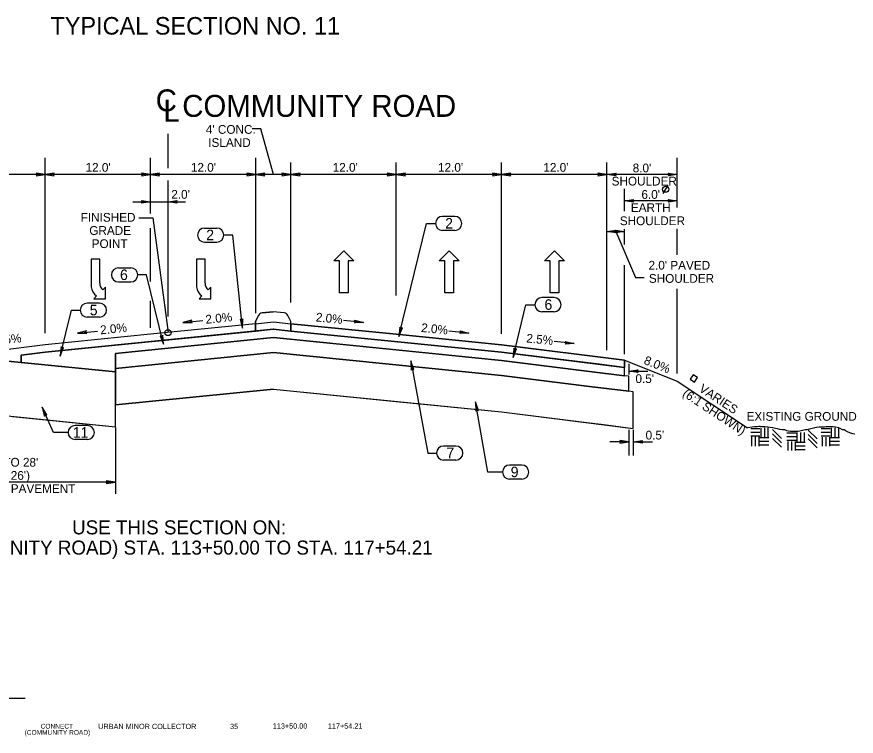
# Model space of a CAD drawing. Extents: x 2003207 to 2014043, y 843846 to 860154.
# Drawn here: x 2013867.8 to 2013963.4, y 844813 to 844894.9 of the extents above; entities that cross this region are included whole.
import ezdxf

# ---------------------------------------------------------------- set-up
doc = ezdxf.new("R2010")
doc.units = 0
for name, color, linetype in [('RD_EX_Road', 7, 'Continuous'), ('RD_EX_Road_txCode', 7, 'Continuous'), ('RD_PD_ConcMed', 7, 'Continuous'), ('RD_QTY_Base_Course', 7, 'Continuous'), ('RD_QTY_ConcPave', 7, 'Continuous'), ('RD_QTY_Intermediate', 7, 'Continuous'), ('RD_QTY_PermVeg', 7, 'Continuous'), ('RD_QTY_Surf_Course', 7, 'Continuous'), ('RD_SHT_Bndy', 7, 'Continuous'), ('RD_SHT_TX', 7, 'Continuous'), ('RD_TX_Misc1', 7, 'Continuous'), ('RD_TX_Misc2', 7, 'Continuous'), ('RD_TX_TypSect', 7, 'Continuous'), ('RD_XS_ExGround', 7, 'Continuous')]:
    doc.layers.add(name, color=color, linetype=linetype)

msp = doc.modelspace()

# ---------------------------------------------------------------- linework, layer by layer
at = {"layer": 'RD_EX_Road'}
for p, q in [((2013879.048, 844854.476), (2013866.048, 844855.776)), ((2013879.048, 844848.226), (2013879.048, 844854.476)), ((2013866.048, 844849.526), (2013879.048, 844848.226)), ((2013867.324, 844849.398), (2013879.048, 844848.226))]:
    msp.add_line(p, q, dxfattribs=at)
at = {"layer": 'RD_EX_Road_txCode'}
msp.add_lwpolyline([(2013944.528, 844853.649), (2013945.028, 844853.318), (2013945.36, 844853.818), (2013944.86, 844854.15)], close=True, dxfattribs=at)
msp.add_circle((2013885.049, 844858.959), 0.35, dxfattribs=at)
at = {"layer": 'RD_PD_ConcMed'}
for p, q in [((2013895.024, 844860.207), (2013895.357, 844860.913)), ((2013895.357, 844860.913), (2013895.024, 844860.207)), ((2013895.76, 844861.197), (2013897.024, 844861.324)), ((2013897.024, 844861.324), (2013895.76, 844861.197)), ((2013898.289, 844861.197), (2013897.024, 844861.324)), ((2013898.289, 844861.197), (2013897.024, 844861.324)), ((2013899.024, 844860.207), (2013898.691, 844860.913)), ((2013899.024, 844860.207), (2013898.691, 844860.913)), ((2013895.024, 844859.124), (2013895.024, 844860.207)), ((2013895.024, 844860.207), (2013895.024, 844859.124)), ((2013899.024, 844859.124), (2013899.024, 844860.207)), ((2013899.024, 844859.124), (2013899.024, 844860.207)), ((2013895.024, 844859.124), (2013897.024, 844859.324)), ((2013895.024, 844859.124), (2013897.024, 844859.324)), ((2013899.024, 844859.124), (2013897.024, 844859.324)), ((2013897.024, 844859.324), (2013899.024, 844859.124))]:
    msp.add_line(p, q, dxfattribs=at)
for centre, start, end in [((2013895.809, 844860.7), 95.71059, 154.75255), ((2013895.809, 844860.7), 95.71059, 154.75255), ((2013898.239, 844860.7), 25.24745, 84.28941), ((2013898.239, 844860.7), 25.24745, 84.28941)]:
    msp.add_arc(centre, 0.5, start, end, dxfattribs=at)
at = {"layer": 'RD_QTY_Base_Course'}
for p, q in [((2013937.048, 844854.029), (2013933.048, 844854.529)), ((2013937.548, 844853.967), (2013937.048, 844854.029)), ((2013937.548, 844852.262), (2013937.548, 844853.967)), ((2013897.048, 844852.507), (2013879.048, 844850.707)), ((2013897.048, 844852.507), (2013911.048, 844851.107)), ((2013933.048, 844852.824), (2013937.548, 844852.262)), ((2013937.548, 844852.262), (2013933.048, 844852.824)), ((2013938.048, 844852.199), (2013937.548, 844852.262)), ((2013938.048, 844852.199), (2013937.548, 844852.262)), ((2013938.048, 844848.032), (2013938.048, 844852.199)), ((2013938.048, 844848.032), (2013938.048, 844852.199)), ((2013911.048, 844851.107), (2013923.048, 844849.907)), ((2013923.048, 844849.907), (2013938.048, 844848.032))]:
    msp.add_line(p, q, dxfattribs=at)
for points in [[(2013933.048, 844854.529), (2013923.048, 844855.779), (2013897.048, 844858.379), (2013879.048, 844856.579), (2013879.048, 844854.874), (2013897.048, 844856.674), (2013923.048, 844854.074), (2013933.048, 844852.824)], [(2013933.048, 844852.824), (2013923.048, 844854.074), (2013897.048, 844856.674), (2013879.048, 844854.874), (2013879.048, 844850.707), (2013897.048, 844852.507), (2013923.048, 844849.907), (2013933.048, 844848.657)], [(2013933.048, 844848.657), (2013934.373, 844848.525), (2013938.048, 844848.032)]]:
    msp.add_lwpolyline(points, dxfattribs=at)
at = {"layer": 'RD_QTY_ConcPave'}
for p, q in [((2013868.307, 844856.383), (2013868.307, 844855.55)), ((2013897.048, 844856.674), (2013879.048, 844854.874)), ((2013897.048, 844856.674), (2013911.048, 844855.274)), ((2013911.048, 844855.274), (2013923.048, 844854.074)), ((2013879.048, 844854.874), (2013879.048, 844850.707)), ((2013923.048, 844854.074), (2013937.548, 844852.262)), ((2013937.548, 844853.967), (2013937.048, 844854.029)), ((2013937.548, 844852.262), (2013937.548, 844853.967))]:
    msp.add_line(p, q, dxfattribs=at)
at = {"layer": 'RD_QTY_Intermediate'}
for p, q in [((2013895.024, 844859.124), (2013871.048, 844856.726)), ((2013897.024, 844859.324), (2013895.024, 844859.124)), ((2013899.024, 844859.124), (2013897.024, 844859.324)), ((2013923.048, 844856.726), (2013899.024, 844859.128)), ((2013899.024, 844859.128), (2013899.024, 844859.124)), ((2013897.048, 844858.379), (2013879.048, 844856.579)), ((2013879.048, 844856.579), (2013897.048, 844858.379)), ((2013897.048, 844858.379), (2013911.048, 844856.979)), ((2013897.048, 844858.379), (2013911.048, 844856.979)), ((2013871.048, 844856.726), (2013868.307, 844856.383)), ((2013879.048, 844856.579), (2013879.048, 844854.874)), ((2013879.048, 844854.476), (2013879.048, 844856.579)), ((2013911.048, 844856.979), (2013923.048, 844855.779)), ((2013911.048, 844856.979), (2013923.048, 844855.779)), ((2013934.145, 844855.339), (2013923.048, 844856.726)), ((2013923.048, 844855.779), (2013937.048, 844854.029)), ((2013923.048, 844855.779), (2013933.048, 844854.529)), ((2013937.048, 844854.976), (2013934.145, 844855.339)), ((2013933.048, 844854.529), (2013937.048, 844854.029)), ((2013937.048, 844854.029), (2013937.048, 844854.976)), ((2013937.048, 844854.029), (2013937.048, 844854.976))]:
    msp.add_line(p, q, dxfattribs=at)
msp.add_lwpolyline([(2013868.307, 844856.383), (2013868.307, 844855.55), (2013879.048, 844854.476)], dxfattribs=at)
msp.add_lwpolyline([(2013912.721, 844855.73), (2013912.759, 844854.681), (2013912.878, 844854.865), (2013913.054, 844854.734)], close=True, dxfattribs=at)
at = {"layer": 'RD_QTY_PermVeg'}
for p, q in [((2013937.048, 844855.809), (2013943.048, 844853.409)), ((2013943.048, 844853.409), (2013951.048, 844848.107))]:
    msp.add_line(p, q, dxfattribs=at)
at = {"layer": 'RD_QTY_Surf_Course'}
for p, q in [((2013895.024, 844859.957), (2013883.048, 844858.759)), ((2013895.024, 844859.957), (2013883.048, 844858.759)), ((2013895.024, 844859.957), (2013897.048, 844860.159)), ((2013895.024, 844859.957), (2013895.024, 844859.124)), ((2013895.024, 844859.124), (2013895.024, 844859.957)), ((2013897.048, 844860.159), (2013899.024, 844859.957)), ((2013899.024, 844859.962), (2013911.048, 844858.759)), ((2013911.048, 844858.759), (2013899.024, 844859.962)), ((2013899.024, 844859.957), (2013899.024, 844859.128)), ((2013897.048, 844859.326), (2013871.048, 844856.726)), ((2013871.048, 844856.726), (2013895.024, 844859.124)), ((2013897.048, 844859.326), (2013923.048, 844856.726)), ((2013899.024, 844859.128), (2013923.048, 844856.726)), ((2013883.048, 844858.759), (2013871.048, 844857.559)), ((2013883.048, 844858.759), (2013871.048, 844857.559)), ((2013911.048, 844858.759), (2013923.048, 844857.559)), ((2013923.048, 844857.559), (2013911.048, 844858.759)), ((2013871.048, 844857.559), (2013845.048, 844854.309)), ((2013871.048, 844857.559), (2013845.048, 844854.309)), ((2013923.048, 844857.559), (2013937.048, 844855.809)), ((2013937.048, 844855.809), (2013923.048, 844857.559)), ((2013871.048, 844856.726), (2013868.307, 844856.383)), ((2013923.048, 844856.726), (2013937.048, 844854.976)), ((2013923.048, 844856.726), (2013937.048, 844854.976)), ((2013937.048, 844855.809), (2013937.048, 844854.976)), ((2013937.048, 844854.976), (2013937.048, 844855.809))]:
    msp.add_line(p, q, dxfattribs=at)
for points in [[(2013899.024, 844859.962), (2013899.024, 844859.957), (2013899.024, 844859.128)], [(2013845.048, 844853.476), (2013853.048, 844854.476), (2013866.048, 844855.776), (2013868.307, 844855.55), (2013868.307, 844856.383), (2013871.048, 844856.726)]]:
    msp.add_lwpolyline(points, dxfattribs=at)
at = {"layer": 'RD_SHT_Bndy'}
msp.add_line((2013868.755, 844817.242), (2013845.755, 844817.242), dxfattribs=at)
at = {"layer": 'RD_TX_Misc2'}
for p, q in [((2013917.712, 844872.191), (2013916.312, 844872.191)), ((2013889.205, 844870.865), (2013890.605, 844870.865)), ((2013917.712, 844870.591), (2013916.312, 844870.591)), ((2013889.205, 844869.265), (2013890.605, 844869.265)), ((2013879.396, 844866.325), (2013880.796, 844866.325)), ((2013879.396, 844864.725), (2013880.796, 844864.725)), ((2013929.032, 844862.933), (2013927.632, 844862.933)), ((2013877.245, 844862.31), (2013875.845, 844862.31)), ((2013929.032, 844861.333), (2013927.632, 844861.333)), ((2013877.245, 844860.71), (2013875.845, 844860.71)), ((2013875.855, 844848.364), (2013874.455, 844848.364)), ((2013875.855, 844846.764), (2013874.455, 844846.764)), ((2013917.839, 844846.026), (2013916.439, 844846.026)), ((2013917.839, 844844.426), (2013916.439, 844844.426)), ((2013925.346, 844843.857), (2013923.946, 844843.857)), ((2013925.346, 844842.257), (2013923.946, 844842.257))]:
    msp.add_line(p, q, dxfattribs=at)
for centre, start, end in [((2013916.312, 844871.391), 90, 270), ((2013917.712, 844871.391), 270, 90), ((2013889.205, 844870.065), 90, 270), ((2013890.605, 844870.065), 270, 90), ((2013879.396, 844865.525), 90, 270), ((2013880.796, 844865.525), 270, 90), ((2013927.632, 844862.133), 90, 270), ((2013929.032, 844862.133), 270, 90), ((2013875.845, 844861.51), 90, 270), ((2013877.245, 844861.51), 270, 90), ((2013874.455, 844847.564), 90, 270), ((2013875.855, 844847.564), 270, 90), ((2013916.439, 844845.226), 90, 270), ((2013917.839, 844845.226), 270, 90), ((2013923.946, 844843.057), 90, 270), ((2013925.346, 844843.057), 270, 90)]:
    msp.add_arc(centre, 0.8, start, end, dxfattribs=at)
at = {"layer": 'RD_TX_TypSect'}
for p, q in [((2013885.049, 844877.676), (2013885.049, 844881.6)), ((2013871.048, 844858.876), (2013871.048, 844878.87)), ((2013883.048, 844872.523), (2013883.048, 844878.87)), ((2013895.048, 844861.182), (2013895.048, 844878.886)), ((2013899.048, 844862.366), (2013899.048, 844878.354)), ((2013911.048, 844863.165), (2013911.048, 844878.354)), ((2013923.048, 844858.816), (2013923.048, 844878.354)), ((2013935.048, 844856.964), (2013935.048, 844878.354)), ((2013943.048, 844873.213), (2013943.048, 844878.87)), ((2013871.048, 844876.963), (2013859.048, 844876.963)), ((2013883.048, 844876.963), (2013871.048, 844876.963)), ((2013895.048, 844876.963), (2013883.048, 844876.963)), ((2013885.049, 844860.768), (2013885.049, 844876.298)), ((2013899.048, 844876.963), (2013895.048, 844876.963)), ((2013911.048, 844876.963), (2013899.048, 844876.963)), ((2013923.048, 844876.963), (2013911.048, 844876.963)), ((2013935.048, 844876.963), (2013923.048, 844876.963)), ((2013943.048, 844876.963), (2013935.048, 844876.963)), ((2013937.048, 844872.778), (2013937.048, 844875.317)), ((2013941.451, 844874.819), (2013942.017, 844875.763)), ((2013881.048, 844873.853), (2013883.048, 844873.853)), ((2013883.048, 844873.853), (2013885.048, 844873.853)), ((2013885.048, 844873.853), (2013887.048, 844873.853)), ((2013943.048, 844873.963), (2013937.048, 844873.963)), ((2013883.048, 844864.767), (2013883.048, 844870.865)), ((2013935.048, 844870.463), (2013937.048, 844870.463)), ((2013937.048, 844869.005), (2013937.048, 844870.735)), ((2013943.048, 844867.806), (2013943.048, 844870.763)), ((2013876.275, 844867.326), (2013876.275, 844864.161)), ((2013877.265, 844867.326), (2013876.275, 844867.326)), ((2013877.265, 844864.581), (2013877.265, 844867.326)), ((2013888.275, 844867.326), (2013888.275, 844864.161)), ((2013889.265, 844867.326), (2013888.275, 844867.326)), ((2013889.265, 844864.581), (2013889.265, 844867.326)), ((2013937.048, 844856.507), (2013937.048, 844866.622)), ((2013877.925, 844864.146), (2013877.61, 844863.831)), ((2013877.91, 844862.796), (2013877.925, 844864.146)), ((2013889.925, 844864.146), (2013889.61, 844863.831)), ((2013889.91, 844862.796), (2013889.925, 844864.146)), ((2013943.048, 844854.274), (2013943.048, 844863.943)), ((2013876.905, 844863.126), (2013876.59, 844862.811)), ((2013876.59, 844862.811), (2013877.91, 844862.796)), ((2013888.905, 844863.126), (2013888.59, 844862.811)), ((2013888.59, 844862.811), (2013889.91, 844862.796)), ((2013883.048, 844859.477), (2013883.048, 844862.569)), ((2013886.729, 844860.096), (2013889.005, 844860.324)), ((2013907.32, 844860.096), (2013905.043, 844860.324)), ((2013874.729, 844858.896), (2013877.005, 844859.124)), ((2013919.32, 844858.896), (2013917.043, 844859.124)), ((2013931.32, 844857.696), (2013929.043, 844857.924)), ((2013937.548, 844855.403), (2013937.548, 844854.175)), ((2013937.548, 844854.544), (2013939.716, 844854.544)), ((2013879.048, 844848.146), (2013879.048, 844840.58)), ((2013937.548, 844847.875), (2013937.548, 844844.962)), ((2013938.048, 844847.875), (2013938.048, 844844.962)), ((2013937.548, 844846.503), (2013935.38, 844846.503)), ((2013938.048, 844846.503), (2013940.216, 844846.503)), ((2013879.048, 844841.898), (2013853.048, 844841.898))]:
    msp.add_line(p, q, dxfattribs=at)
for points in [[(2013897.048, 844876.963), (2013895.625, 844882.181), (2013894.637, 844882.181)], [(2013881.731, 844872.046), (2013883.301, 844872.046), (2013885.049, 844858.959)], [(2013911.352, 844858.518), (2013914.503, 844871.391), (2013915.512, 844871.391)], [(2013936.048, 844870.463), (2013938.288, 844865.217), (2013939.276, 844865.217)], [(2013893.512, 844859.471), (2013892.414, 844870.065), (2013891.405, 844870.065)], [(2013884.539, 844857.626), (2013882.605, 844865.525), (2013881.596, 844865.525)], [(2013924.351, 844856.119), (2013925.823, 844862.133), (2013926.832, 844862.133)], [(2013872.754, 844856.27), (2013874.037, 844861.51), (2013875.045, 844861.51)], [(2013912.721, 844855.73), (2013914.63, 844845.226), (2013915.639, 844845.226)], [(2013873.655, 844847.564), (2013871.989, 844847.564), (2013870.692, 844850.456)], [(2013923.146, 844843.057), (2013921.481, 844843.057), (2013920.067, 844851.055)]]:
    msp.add_lwpolyline(points, dxfattribs=at)
for points in [[(2013871.048, 844876.963), (2013870.009, 844877.113), (2013870.169, 844876.963), (2013870.009, 844876.813)], [(2013871.048, 844876.963), (2013872.087, 844876.813), (2013871.927, 844876.963), (2013872.087, 844877.113)], [(2013883.048, 844876.963), (2013882.009, 844877.113), (2013882.169, 844876.963), (2013882.009, 844876.813)], [(2013883.048, 844876.963), (2013884.087, 844876.813), (2013883.927, 844876.963), (2013884.087, 844877.113)], [(2013895.048, 844876.963), (2013894.009, 844877.113), (2013894.169, 844876.963), (2013894.009, 844876.813)], [(2013895.048, 844876.963), (2013896.087, 844876.813), (2013895.927, 844876.963), (2013896.087, 844877.113)], [(2013899.048, 844876.963), (2013898.009, 844877.113), (2013898.169, 844876.963), (2013898.009, 844876.813)], [(2013899.048, 844876.963), (2013900.087, 844876.813), (2013899.927, 844876.963), (2013900.087, 844877.113)], [(2013911.048, 844876.963), (2013910.009, 844877.113), (2013910.169, 844876.963), (2013910.009, 844876.813)], [(2013911.048, 844876.963), (2013912.087, 844876.813), (2013911.927, 844876.963), (2013912.087, 844877.113)], [(2013923.048, 844876.963), (2013922.009, 844877.113), (2013922.169, 844876.963), (2013922.009, 844876.813)], [(2013923.048, 844876.963), (2013924.087, 844876.813), (2013923.927, 844876.963), (2013924.087, 844877.113)], [(2013935.048, 844876.963), (2013934.009, 844877.113), (2013934.169, 844876.963), (2013934.009, 844876.813)], [(2013935.048, 844876.963), (2013936.087, 844877.113), (2013935.927, 844876.963), (2013936.087, 844876.813)], [(2013943.048, 844876.963), (2013942.009, 844876.813), (2013942.169, 844876.963), (2013942.009, 844877.113)], [(2013883.048, 844873.853), (2013882.009, 844873.703), (2013882.169, 844873.853), (2013882.009, 844874.003)], [(2013885.048, 844873.853), (2013886.087, 844874.003), (2013885.927, 844873.853), (2013886.087, 844873.703)], [(2013937.048, 844873.963), (2013938.087, 844874.113), (2013937.927, 844873.963), (2013938.087, 844873.813)], [(2013943.048, 844873.963), (2013942.009, 844873.813), (2013942.169, 844873.963), (2013942.009, 844874.113)], [(2013935.048, 844870.463), (2013936.087, 844870.613), (2013935.927, 844870.463), (2013936.087, 844870.313)], [(2013937.048, 844870.463), (2013936.009, 844870.313), (2013936.169, 844870.463), (2013936.009, 844870.613)], [(2013905.552, 844863.471), (2013904.592, 844863.471), (2013904.592, 844867.14), (2013903.941, 844867.14), (2013905.072, 844868.271), (2013906.204, 844867.14), (2013905.552, 844867.14)], [(2013917.552, 844863.471), (2013916.592, 844863.471), (2013916.592, 844867.14), (2013915.941, 844867.14), (2013917.072, 844868.271), (2013918.204, 844867.14), (2013917.552, 844867.14)], [(2013929.552, 844863.471), (2013928.592, 844863.471), (2013928.592, 844867.14), (2013927.941, 844867.14), (2013929.072, 844868.271), (2013930.204, 844867.14), (2013929.552, 844867.14)], [(2013886.729, 844860.096), (2013887.777, 844860.051), (2013887.603, 844860.184), (2013887.747, 844860.349)], [(2013893.512, 844859.471), (2013893.55, 844860.52), (2013893.418, 844860.345), (2013893.252, 844860.488)], [(2013907.32, 844860.096), (2013906.271, 844860.051), (2013906.446, 844860.184), (2013906.301, 844860.349)], [(2013874.729, 844858.896), (2013875.777, 844858.851), (2013875.603, 844858.984), (2013875.747, 844859.149)], [(2013911.352, 844858.518), (2013911.745, 844859.491), (2013911.561, 844859.372), (2013911.453, 844859.563)], [(2013919.32, 844858.896), (2013918.271, 844858.851), (2013918.446, 844858.984), (2013918.301, 844859.149)], [(2013884.539, 844857.626), (2013884.438, 844858.671), (2013884.33, 844858.48), (2013884.146, 844858.599)], [(2013872.754, 844856.27), (2013873.147, 844857.243), (2013872.963, 844857.124), (2013872.855, 844857.315)], [(2013924.351, 844856.119), (2013924.743, 844857.093), (2013924.56, 844856.973), (2013924.452, 844857.164)], [(2013931.32, 844857.696), (2013930.271, 844857.651), (2013930.446, 844857.784), (2013930.301, 844857.949)], [(2013937.548, 844854.544), (2013938.587, 844854.694), (2013938.427, 844854.544), (2013938.587, 844854.394)], [(2013870.692, 844850.456), (2013870.977, 844849.446), (2013871.049, 844849.653), (2013871.251, 844849.568)], [(2013920.067, 844851.055), (2013920.1, 844850.006), (2013920.22, 844850.19), (2013920.395, 844850.059)], [(2013937.548, 844846.503), (2013936.509, 844846.653), (2013936.669, 844846.503), (2013936.509, 844846.353)], [(2013938.048, 844846.503), (2013939.087, 844846.653), (2013938.927, 844846.503), (2013939.087, 844846.353)], [(2013879.048, 844841.898), (2013878.009, 844842.048), (2013878.169, 844841.898), (2013878.009, 844841.749)]]:
    msp.add_lwpolyline(points, close=True, dxfattribs=at)
msp.add_circle((2013941.734, 844875.291), 0.35, dxfattribs=at)
for centre, radius, start, end in [((2013877.828, 844864.398), 1.576, 188.67607, 233.98777), ((2013878.243, 844864.578), 0.983, 180, 229.65817), ((2013889.828, 844864.398), 1.576, 188.67607, 233.98777), ((2013890.243, 844864.578), 0.983, 180, 229.65817)]:
    msp.add_arc(centre, radius, start, end, dxfattribs=at)
at = {"layer": 'RD_XS_ExGround'}
for p, q in [((2013952.461, 844847.995), (2013951.42, 844847.995)), ((2013952.461, 844847.578), (2013951.42, 844847.578)), ((2013952.558, 844848.092), (2013952.558, 844847.05)), ((2013952.974, 844848.092), (2013952.974, 844847.05)), ((2013953.391, 844848.092), (2013953.391, 844847.05)), ((2013954.914, 844846.901), (2013953.914, 844847.901)), ((2013956.598, 844847.476), (2013955.556, 844847.476)), ((2013956.694, 844847.573), (2013956.694, 844846.532)), ((2013957.111, 844847.573), (2013957.111, 844846.532)), ((2013957.527, 844847.573), (2013957.527, 844846.532)), ((2013958.982, 844846.828), (2013957.982, 844847.828)), ((2013960.488, 844847.99), (2013959.446, 844847.99)), ((2013960.488, 844847.573), (2013959.446, 844847.573)), ((2013960.585, 844848.087), (2013960.585, 844847.045)), ((2013961.001, 844848.087), (2013961.001, 844847.045)), ((2013961.418, 844848.087), (2013961.418, 844847.045)), ((2013952.461, 844847.162), (2013951.42, 844847.162)), ((2013951.524, 844847.057), (2013951.524, 844846.016)), ((2013951.941, 844847.057), (2013951.941, 844846.016)), ((2013952.357, 844847.057), (2013952.357, 844846.016)), ((2013953.503, 844846.953), (2013952.461, 844846.953)), ((2013953.503, 844846.537), (2013952.461, 844846.537)), ((2013954.914, 844846.401), (2013953.914, 844847.401)), ((2013954.914, 844845.901), (2013953.914, 844846.901)), ((2013956.598, 844847.06), (2013955.556, 844847.06)), ((2013956.598, 844846.643), (2013955.556, 844846.643)), ((2013955.66, 844846.539), (2013955.66, 844845.497)), ((2013956.077, 844846.539), (2013956.077, 844845.497)), ((2013956.493, 844846.539), (2013956.493, 844845.497)), ((2013958.982, 844846.328), (2013957.982, 844847.328)), ((2013958.982, 844845.828), (2013957.982, 844846.828)), ((2013960.488, 844847.157), (2013959.446, 844847.157)), ((2013959.551, 844847.053), (2013959.551, 844846.011)), ((2013959.967, 844847.053), (2013959.967, 844846.011)), ((2013960.384, 844847.053), (2013960.384, 844846.011)), ((2013961.53, 844846.948), (2013960.488, 844846.948)), ((2013961.53, 844846.532), (2013960.488, 844846.532)), ((2013953.503, 844846.12), (2013952.461, 844846.12)), ((2013957.639, 844846.435), (2013956.598, 844846.435)), ((2013957.639, 844846.018), (2013956.598, 844846.018)), ((2013957.639, 844845.601), (2013956.598, 844845.601)), ((2013961.53, 844846.115), (2013960.488, 844846.115))]:
    msp.add_line(p, q, dxfattribs=at)
msp.add_lwpolyline([(2013963.274, 844847.375), (2013963.054, 844847.411), (2013962.835, 844847.485), (2013962.542, 844847.595), (2013962.285, 844847.704), (2013962.066, 844847.851), (2013961.883, 844847.888), (2013961.627, 844848.034), (2013961.407, 844848.107), (2013961.078, 844848.181), (2013960.821, 844848.217), (2013960.528, 844848.217), (2013960.199, 844848.217), (2013960.016, 844848.217), (2013959.833, 844848.181), (2013959.613, 844848.181), (2013959.394, 844848.181), (2013959.211, 844848.181), (2013958.918, 844848.144), (2013958.735, 844848.107), (2013958.405, 844848.034), (2013958.113, 844847.961), (2013957.82, 844847.888), (2013957.637, 844847.851), (2013957.307, 844847.778), (2013957.015, 844847.704), (2013956.795, 844847.668), (2013956.612, 844847.668), (2013956.392, 844847.668), (2013956.173, 844847.668), (2013955.953, 844847.668), (2013955.733, 844847.704), (2013955.55, 844847.741), (2013955.294, 844847.851), (2013955.038, 844847.888), (2013954.745, 844847.924), (2013954.489, 844847.997), (2013954.233, 844848.034), (2013953.94, 844848.107), (2013953.647, 844848.144), (2013953.354, 844848.181), (2013953.025, 844848.217), (2013952.732, 844848.217), (2013952.512, 844848.254), (2013952.329, 844848.254), (2013952.146, 844848.217), (2013951.853, 844848.217), (2013951.597, 844848.181), (2013951.341, 844848.144), (2013951.048, 844848.107)], dxfattribs=at)

# ---------------------------------------------------------------- texts
at = {"layer": 'RD_EX_Road_txCode'}
for s, p in [('USE THIS SECTION ON:', (2013874.116, 844835.955)), ('CONNECT (S-2885 COMMUNITY ROAD) STA. 113+50.00 TO STA. 117+54.21', (2013839.325, 844833.649))]:
    msp.add_text(s, height=1.6, dxfattribs=at).set_placement(p)
at = {"layer": 'RD_SHT_TX'}
for s, height, p in [('CONNECT ', 0.5415, (2013870.534, 844813.822)), ('URBAN MINOR COLLECTOR', 0.6, (2013877.091, 844813.768)), ('35', 0.6, (2013892.109, 844813.768)), ('113+50.00', 0.6, (2013896.976, 844813.817)), ('117+54.21', 0.6, (2013903.254, 844813.817)), ('(COMMUNITY ROAD)', 0.5415, (2013868.706, 844813.117))]:
    msp.add_text(s, height=height, dxfattribs=at).set_placement(p)
at = {"layer": 'RD_TX_Misc1'}
for s, p in [('C', (2013883.64, 844884.166)), ('COMMUNITY ROAD', (2013886.667, 844883.537)), ('L', (2013884.518, 844882.985))]:
    msp.add_text(s, height=2.5, dxfattribs=at).set_placement(p)
at = {"layer": 'RD_TX_Misc2'}
for s, p in [('2', (2013916.616, 844870.806)), ('2', (2013889.395, 844869.48)), ('6', (2013879.575, 844864.941)), ('6', (2013927.925, 844861.548)), ('5', (2013876.127, 844860.925)), ('11', (2013874.194, 844846.979)), ('7', (2013916.755, 844844.641)), ('9', (2013924.082, 844842.473))]:
    msp.add_text(s, height=1.2, dxfattribs=at).set_placement(p)
at = {"layer": 'RD_TX_TypSect'}
for s, height, p in [('TYPICAL SECTION NO. 11', 2, (2013871.648, 844892.912)), ("4' CONC.", 1, (2013889.355, 844881.607)), ('ISLAND', 1, (2013889.63, 844880.107)), ("12.0'", 1, (2013875.65, 844877.28)), ("12.0'", 1, (2013887.65, 844877.28)), ("12.0'", 1, (2013903.802, 844877.28)), ("12.0'", 1, (2013915.802, 844877.28)), ("12.0'", 1, (2013927.802, 844877.28)), ("8.0'", 1, (2013937.979, 844877.213)), ('SHOULDER', 1, (2013935.579, 844875.713)), ("2.0'", 1, (2013885.415, 844874.203)), ("6.0'", 1, (2013938.973, 844874.195)), ('EARTH', 1, (2013937.769, 844872.695)), ('FINISHED', 1, (2013875.097, 844871.586)), ('SHOULDER', 1, (2013936.509, 844871.195)), ('GRADE', 1, (2013876.073, 844870.086)), ('POINT', 1, (2013876.349, 844868.586)), ("2.0' PAVED", 1, (2013939.78, 844866.124)), ('SHOULDER', 1, (2013939.82, 844864.624)), ("0.5'", 1, (2013938.295, 844853.205)), ('EXISTING GROUND', 1, (2013950.948, 844848.904)), ("0.5'", 1, (2013939.446, 844846.767)), ("VARIES 22' TO 28'", 1, (2013858.897, 844843.673)), ("(SHOWN 26')", 1, (2013861.188, 844842.173)), ('RETAIN EXISTING PAVEMENT', 1, (2013855.243, 844840.673))]:
    msp.add_text(s, height=height, dxfattribs=at).set_placement(p)
for s, rotation, p in [('2.0%', 5.71059, (2013889.362, 844859.95)), ('2.0%', 354.28941, (2013901.843, 844860.234)), ('2.0%', 5.71059, (2013877.362, 844858.75)), ('2.0%', 354.28941, (2013913.843, 844859.034)), ('2.5%', 5.71059, (2013865.346, 844857.548)), ('2.5%', 354.28941, (2013925.827, 844857.836)), ('8.0%', 338.19859, (2013939.171, 844855.408)), ('(6:1 SHOWN)', 326.46577, (2013943.562, 844851.778)), ('VARIES', 326.46577, (2013945.447, 844852.328))]:
    msp.add_text(s, height=1, rotation=rotation, dxfattribs=at).set_placement(p)

doc.saveas('drawing.dxf')
